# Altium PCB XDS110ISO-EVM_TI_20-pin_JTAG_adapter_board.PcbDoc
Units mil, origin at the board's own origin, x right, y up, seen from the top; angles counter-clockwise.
Board outline 1100 x 500.17 mil, 2 copper layers (Top Signal, Bottom Signal), stack 58.8 mil thick; 2 components, 6 nets, 35 pads, 16 vias.
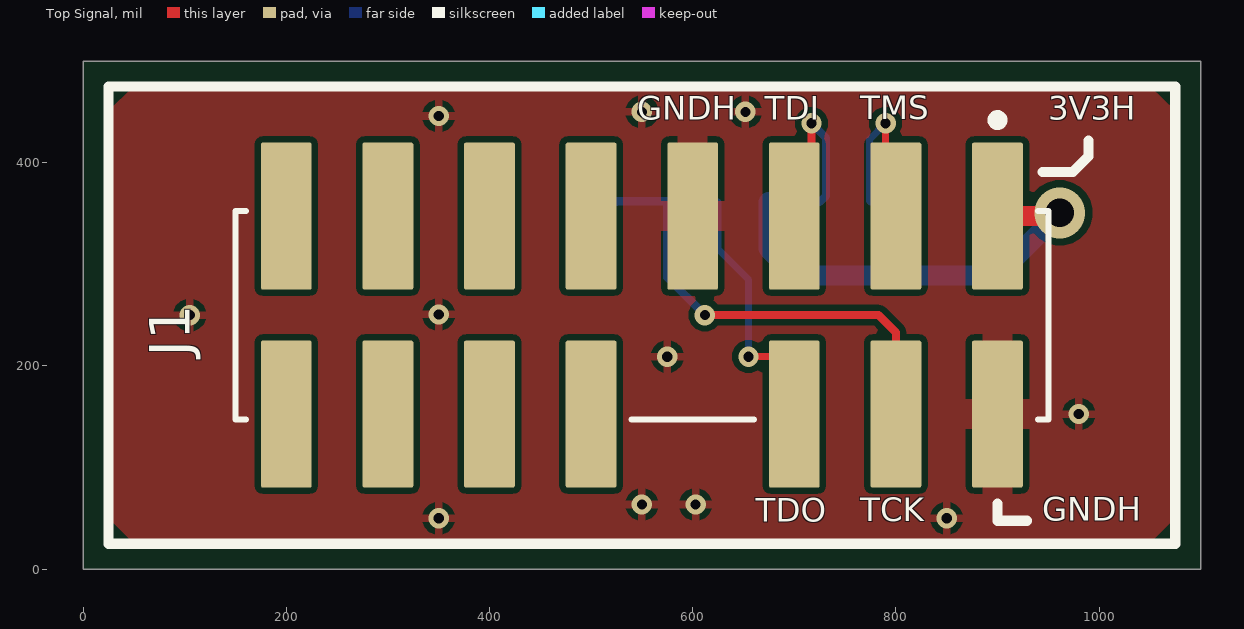
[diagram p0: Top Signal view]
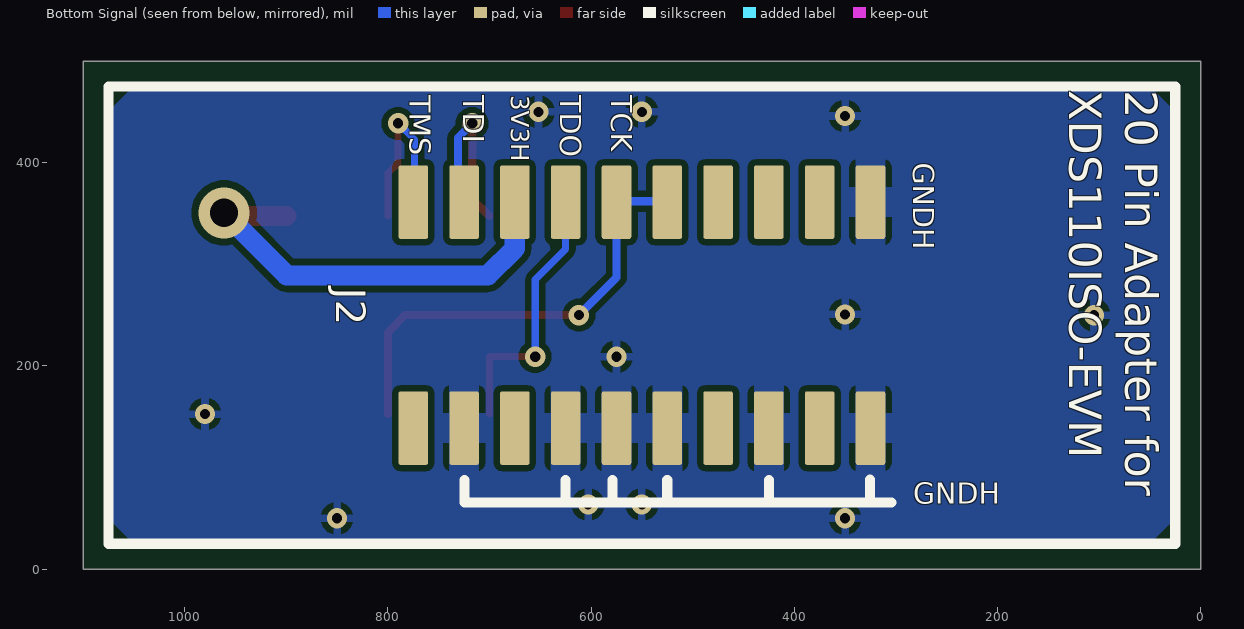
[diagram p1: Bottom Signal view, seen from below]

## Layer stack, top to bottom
Top Solder: solder mask 0.4, Solder Resist, Dk 3.5
Top Signal: signal copper 1.4
Dielectric 1: prepreg 8, FR-4, Dk 4.2
Dielectric 2: core 40, FR-4, Dk 4.2
Dielectric 3: prepreg 8, FR-4, Dk 4.2
Bottom Signal: signal copper 1.4
Bottom Solder: solder mask 0.4, Solder Resist, Dk 3.5

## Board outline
0,-0.17 0,500 1100,500 1100,-0.17

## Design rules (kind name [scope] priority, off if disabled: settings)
AcuteAngle [All] p1: minimum=4.50000000000000E+0001 checktracksonly=TRUE
AssemblyTestPointUsage [All] p1: valid=2
BoardOutlineClearance BoardOutlineClearance_MountingHoles [OnCopper and InComponentClass('Mounting Holes')] p1: gap=40 ignorepadtopadclearanceinfootprint=FALSE
BoardOutlineClearance BoardOutlineClearance_Poly [OnCopper and IsPoly] p2: gap=25 ignorepadtopadclearanceinfootprint=FALSE
BoardOutlineClearance BoardOutlineClearance_USB101 [InComponent('USB101')] p3: gap=0 ignorepadtopadclearanceinfootprint=FALSE
BoardOutlineClearance [OnCopper and Not InComponentClass('Logo') and not InComponentClass('FiducialMark') and not InRegion(1000,500,4000,800) and not InPoly] p4: gap=10 ignorepadtopadclearanceinfootprint=FALSE
Clearance Clearance_NPTH [HoleDiameter = 39] p1: gap=15 ignorepadtopadclearanceinfootprint=FALSE
Clearance Clearance_PTH [HoleDiameter > 10] p2: gap=7 ignorepadtopadclearanceinfootprint=FALSE
Clearance Clearance_FiducialMark [InComponentClass('FiducialMark') vs InComponentClass('FiducialMark')] p3: gap=0 ignorepadtopadclearanceinfootprint=FALSE
Clearance Clearance_Boardedge [All vs IsKeepOut] p4: gap=11.8 ignorepadtopadclearanceinfootprint=FALSE
Clearance [All] p5: gap=6 ignorepadtopadclearanceinfootprint=FALSE
ComponentClearance "ComponentClearance_overlay to overlay" [OnBottomSilkscreen vs OnTopSilkscreen] p1: gap=0 collisioncheckmode=3 verticalgap=0 showdistances=FALSE
ComponentClearance ComponentClearance_MountingHoles_FiducialMarks [InComponentClass('Mounting Holes') vs InComponentClass('FiducialMark')] p2: gap=50 collisioncheckmode=3 verticalgap=10 showdistances=FALSE
ComponentClearance ComponentClearance_Shunt [InComponentClass('Header') vs InComponentClass('Shunt')] p3: gap=0 collisioncheckmode=3 verticalgap=0 showdistances=FALSE
ComponentClearance ComponentClearance_Logo [InComponentClass('Logo')] p4: gap=0 collisioncheckmode=3 verticalgap=0 showdistances=FALSE
ComponentClearance ComponentClearance_Logo_1 [InComponentClass('Logo') vs InComponentClass('Logo')] p5: gap=0 collisioncheckmode=3 verticalgap=0 showdistances=FALSE
ComponentClearance ComponentClearance_ScrewToNut [(HasFootprint('NY PMS 440 0025 PH')) vs (HasFootprint('Keystone_1902C'))] p6: gap=3.94 collisioncheckmode=3 verticalgap=3.94 showdistances=FALSE
ComponentClearance ComponentClearance_MountingHoles [InComponentClass('Mounting Holes')] p7 off: gap=250 collisioncheckmode=3 verticalgap=100000 showdistances=FALSE
ComponentClearance ComponentClearance_SmallPassives [HasFootprint('0201*') or HasFootprint('0402*') or HasFootprint('0508') or HasFootprint('0603*') or HasFootprint('0612') or HasFootprint('0805*') or HasFootprint('0815*') or HasFootprint('0830*') or HasFootprint('1206*') or HasFootprint('1210*') or HasFootprint('1808*') or HasFootprint('1812*') or HasFootprint('1825*') or HasFootprint('2010*') or HasFootprint('2220*') or HasFootprint('2225*') or HasFootprint('2512*') or HasFootprint('2728*') or HasFootprint('3518*') vs HasFootprint('0201*') or HasFootprint('0402*') or HasFootprint('0508') or HasFootprint('0603*') or HasFootprint('0612') or HasFootprint('0805*') or HasFootprint('0815*') or HasFootprint('0830*') or HasFootprint('1206*') or HasFootprint('1210*') or HasFootprint('1808*') or HasFootprint('1812*') or HasFootprint('1825*') or HasFootprint('2010*') or HasFootprint('2220*') or HasFootprint('2225*') or HasFootprint('2512*') or HasFootprint('2728*') or HasFootprint('3518*')] p8 off: gap=10 collisioncheckmode=3 verticalgap=0 showdistances=FALSE
ComponentClearance ComponentClearance_THtoSMT [IsThruComponent vs IsSMTComponent] p9 off: gap=10 collisioncheckmode=3 verticalgap=10 showdistances=FALSE
ComponentClearance ComponentClearance_THtoTH [IsThruComponent vs IsThruComponent] p10 off: gap=20 collisioncheckmode=3 verticalgap=30 showdistances=FALSE
DiffPairsRouting [All] p1: maxlimit=100 minlimit=6 mostfreqgap=6 toplayer_minwidth=5.91 toplayer_maxwidth=15 toplayer_prefwidth=10.63 bottomlayer_minwidth=5.91 bottomlayer_maxwidth=15 bottomlayer_prefwidth=10.63 maxuncoupledlength=1000
FabricationTestPointUsage TestPointUsage [All] p1: valid=2 allowmultiple=FALSE
FabricationTestpoint Testpoint [All] p1: side=3 testpointundercomponent=TRUE minsize=40 maxsize=100 preferedsize=60 minholesize=0 maxholesize=40 preferedholesize=32 testpointgrid=1 allowsidetop=TRUE allowsidebottom=TRUE usegrid=TRUE gridtolerance=0.01
FanoutControl Fanout_LCC [IsLCC] p1: bgadir=Out bgaviamode=Centered fanoutstyle=Auto fanoutdirection=Alternating viagrid=1 // Fanout_LCC (Default Rule)
FanoutControl Fanout_BGA [IsBGA] p2: bgadir=Out bgaviamode=Centered fanoutstyle=Auto fanoutdirection=Alternating viagrid=1 // Fanout_BGA (Default Rule)
FanoutControl Fanout_Default [All] p4: bgadir=Out bgaviamode=Centered fanoutstyle=Auto fanoutdirection=Alternating viagrid=1 // Fanout_Default (Default Rule)
FanoutControl Fanout_Small [(CompPinCount < 5)] p5: bgadir=Out bgaviamode=Centered fanoutstyle=Auto fanoutdirection=OutThenIn viagrid=1 // Fanout_Small (Default Rule)
HoleSize [All] p1: absolutevalues=TRUE maxlimit=251 minlimit=7.87 maxpercent=80.000 minpercent=20.000
HoleToHoleClearance HoleToHoleClearance_USB101 [InComponent('USB101') vs InComponent('USB101')] p1: gap=0 allowstackedmicrovias=TRUE
HoleToHoleClearance [All] p2: gap=12 allowstackedmicrovias=TRUE
MatchedLengths FSIRX [InNetClass('FSIRX')] p1: tolerance=25 checknetsindiffpair=FALSE checkdiffpairvsdiffpair=TRUE checkxsignals=TRUE checkothers=TRUE
MatchedLengths FSITX [InNetClass('FSITX')] p2: tolerance=25 checknetsindiffpair=FALSE checkdiffpairvsdiffpair=TRUE checkxsignals=TRUE checkothers=TRUE
MinimumAnnularRing MinimumAnnularRing_ThermalPadVias [IsVia and InAnyComponent] p1: minimumring=5
MinimumAnnularRing [All] p2: minimumring=5
MinimumSolderMaskSliver MinimumSolderMaskSliver_Logo [InComponentClass('Logo') vs InComponentClass('Logo')] p1: minsoldermaskwidth=0.7
MinimumSolderMaskSliver [All] p2: minsoldermaskwidth=0
PlaneClearance [All] p1: clearance=6
PlaneConnect [All] p1: planeconnectstyle=Relief reliefexpansion=7 reliefentries=4 reliefconductorwidth=8 reliefairgap=6
PolygonConnect PolygonConnect_via [isvia] p1: connectstyle=Relief reliefconductorwidth=8 reliefentries=4 polygonreliefangle="90 Angle" airgapwidth=6
PolygonConnect PolygonConnect_GNDH [InNet('GNDH') OR InNet('+3V3H')] p2: connectstyle=Relief reliefconductorwidth=30 reliefentries=4 polygonreliefangle="90 Angle" airgapwidth=6
PolygonConnect [All] p3: connectstyle=Relief reliefconductorwidth=8 reliefentries=4 polygonreliefangle="90 Angle" airgapwidth=6
RoutingVias RoutingVias_PWR [InNet('+3V3H')] p1: holewidth=28 width=50 viastyle="Through Hole" minholewidth=28 minwidth=50 maxholewidth=28 maxwidth=50
RoutingVias ThermalPadVias [All] p2: holewidth=10 width=20 viastyle="Through Hole" minholewidth=10 minwidth=20 maxholewidth=20 maxwidth=40
RoutingVias [All] p3: holewidth=10 width=20 viastyle="Through Hole" minholewidth=10 minwidth=20 maxholewidth=20 maxwidth=40
SilkToBoardRegionClearance [Not ((IsComment or IsDesignator) And (Hide <> 'False')) and not InRegion(1000,500,4000,800)] p1:
SilkToSilkClearance SilkToSilkClearance_Pb-FreeLogo [(HasFootprint('Pb-Free_Overlay_Medium') OR HasFootprint('Pb-Free_Overlay_Small')) vs (HasFootprint('Pb-Free_Overlay_Medium') OR HasFootprint('Pb-Free_Overlay_Small'))] p1: silktosilkclearance=0
SilkToSilkClearance [All] p2: silktosilkclearance=3
SilkToSolderMaskClearance SilkToComponentPadClearance [(IsPad or IsFill or IsRegion) and InAnycomponent] p1: minsilkscreentomaskgap=2.5 clearancetoexposedcopper=TRUE
SilkToSolderMaskClearance "Silk to Solder Mask Opening" [All] p2: minsilkscreentomaskgap=2.5 clearancetoexposedcopper=TRUE
SolderMaskExpansion [All] p1: expansion=2 istentingtop=FALSE
UnRoutedNet [All] p1: checkbadconnections=TRUE
Width Analog [InNetClass('Analog')] p1: maxlimit=25 minlimit=8 preferedwidth=8
Width [All] p2: maxlimit=100 minlimit=7 preferedwidth=8 minimp=50.000000 maximp=50.000000 favimp=50.000000 checkconnectedcopper=TRUE
12 further rules are at their usual default settings.

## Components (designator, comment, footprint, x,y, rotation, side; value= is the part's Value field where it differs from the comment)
J1 "TSM-108-01-L-DV-008-P-TR" FP-TSM-108-01-L-DV-008-P-TR_HDR15-MFG 550,250 r180 top
J2 "RSM-110-02-L-D" Samtec_RSM-110-02-x-D 550,250 r180 bottom

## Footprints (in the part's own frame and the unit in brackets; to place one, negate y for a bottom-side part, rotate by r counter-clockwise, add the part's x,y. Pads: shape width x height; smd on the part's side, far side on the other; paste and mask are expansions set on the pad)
FP-TSM-108-01-L-DV-008-P-TR_HDR15-MFG [mm]
  rrect8% 1.27x3.68 smd paste+0 mask+0: 1(-8.89,-2.475) 2(-8.89,2.475) 3(-6.35,-2.475) 4(-6.35,2.475) 5(-3.81,-2.475) 6(-3.81,2.475) 7(-1.27,-2.475) 9(1.27,-2.475) 10(1.27,2.475) 11(3.81,-2.475) 12(3.81,2.475) 13(6.35,-2.475) 14(6.35,2.475) 15(8.89,-2.475) 16(8.89,2.475)
  silkscreen extent -10.16,-5 10.16,2.6, body extent -10.26,-4.42 10.26,4.42, height 0.25
Samtec_RSM-110-02-x-D [mm] "Receptacle, 1.27mm, 10x2, SMT"
  rrect14% 0.74x1.84 smd: 1(-5.715,2.825) 2(-5.715,-2.825) 3(-4.445,2.825) 4(-4.445,-2.825) 5(-3.175,2.825) 6(-3.175,-2.825) 7(-1.905,2.825) 8(-1.905,-2.825) 9(-0.635,2.825) 10(-0.635,-2.825) 11(0.635,2.825) 12(0.635,-2.825) 13(1.905,2.825) 14(1.905,-2.825) 15(3.175,2.825) 16(3.175,-2.825) 17(4.445,2.825) 18(4.445,-2.825) 19(5.715,2.825) 20(5.715,-2.825)
  body extent -6.48,-3.24 6.48,3.24, height 6.1

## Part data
J1: library part CMP-0121706-1, "Conn Unshrouded HDR 16 POS 2.54mm Solder ST SMT", Manufacturer=Samtec, Operating Temperature Range="-55°C to +125°C"
J2: library part CMP-0081743-1, "Receptacle, 1.27mm, 10x2, Gold with Tin tail, SMT", Color=Black, Current_A=3.1A, Manufacturer=Samtec, Supplier Part Number 1=SAM9848-ND

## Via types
v1: diameter 20, hole 10, Top Signal to Bottom Signal, tented both sides, 15 vias
v2: diameter 50, hole 28, Top Signal to Bottom Signal, tented both sides, 1 vias

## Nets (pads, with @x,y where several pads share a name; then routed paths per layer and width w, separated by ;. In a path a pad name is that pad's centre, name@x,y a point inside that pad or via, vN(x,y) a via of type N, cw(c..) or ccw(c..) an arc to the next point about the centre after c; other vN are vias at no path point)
MCU_TDO: J1.6 J2.7 | length 266.1
  Top Signal w7: v1(655,209.06) 700,209.06 J1.6
  Bottom Signal w7: J2.7 625,315 655,285 v1(655,209.06)
+3V3H: J1.1 J2.5 | length 431.1
  Top Signal w20: J1.1 958.17,347.44 v2(961.29,350.55)
  Bottom Signal w20: J2.5 675,315.49 701.49,289 775,289 899.73,289 v2(961.29,350.55)
GNDH: J1.2 J1.7 J2.4 J2.8 J2.10 J2.12 J2.16 J2.19 J2.20
  other v1: 350,50 850,50 550,63.56 602.94,63.56 980,152.56 575,209.06 105,249.99 350,250.65 350,446 550,450 651.82,450
MCU_TCK: J1.4 J2.9 J2.11 | length 453.6
  Top Signal w8: v1(612,249.99) 783,249.99 800,232.99 J1.4
  Bottom Signal w8: J2.11 525,361.99 575,361.99 J2.9 575,286.99 v1(612,249.99)
MCU_TDI: J1.5 J2.3 | length 184.3
  Top Signal w8: J1.5 717,364.44 v1(717,438.75)
  Bottom Signal w8: v1(717,438.75) 731.16,424.59 731.16,367.38 J2.3
MCU_TMS: J1.3 J2.1 | length 180.1
  Top Signal w7: v1(789.88,438.75) 789.88,400 800,389.88 J1.3
  Bottom Signal w7: J2.1 773.88,362.34 773.88,422.75 v1(789.88,438.75)
pads on no net: J1.9 J1.10 J1.11 J1.12 J1.13 J1.14 J1.15 J1.16 J2.2 J2.6 J2.13 J2.14 J2.15 J2.17 J2.18

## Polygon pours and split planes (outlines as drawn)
GNDH on Bottom Signal "NONET_L-01_P-001" (solid, remove dead copper, pour order 22): 1050,475 50,475 25,450 25,50 50,25 1050,25 1075,50 1075,450
GNDH on Top Signal "NONET_L-01_P-001" (solid, remove dead copper, pour order 15): 50,475 25,450.81 25,50.49 50,25.49 1050,25.49 1075,50.49 1075.22,450.81 1050,475

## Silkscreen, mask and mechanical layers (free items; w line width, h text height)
Top Overlay:
  lines w10: 900,64.38 900,47.63 928.89,47.63 ; 944.39,390.81 974.21,390.81 989.65,406.25 989.65,421.82 ; 25,25 1075,25 1075,475 25,475 25,25
  text "TMS" at 765,434.8 h40
  text "GNDH" at 545.56,434.3 h40
  text "TDI" at 670.72,434.3 h40
  text "3V3H" at 950,434.3 h40
  text "GNDH" at 943.94,39.64 h40
  text "TDO" at 662.24,38.73 h40
  text "TCK" at 765,39.22 h40
Bottom Overlay:
  lines w10: 25,474.51 25,25 1075,25 1075,474.51 ; 25,475 1075,475 ; 304.28,65.53 724.44,65.53 724.44,87.4 ; 325.51,65.53 325.51,87.91 ; 425,65.53 425,87.4 ; 525,65.53 525,87.4 ; 579,65.53 579,87.4 ; 625.01,65.53 625.01,87.4
  text "20 Pin Adapter for / XDS110ISO-EVM" at 140,471.48 h55 r90
  text "TCK" at 587,466.57 h35 r90
  text "TDO" at 637.16,466.57 h35 r90
  text "3V3H" at 684.51,466.57 h30 r90
  text "TDI" at 732.87,466.57 h35 r90
  text "TMS" at 785.57,466.57 h35 r90
  text "GNDH" at 289.63,400 h35 r90
  text "GNDH" at 283,57.37 h35
M1 Board Outline:
  the board outline again, w10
